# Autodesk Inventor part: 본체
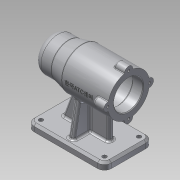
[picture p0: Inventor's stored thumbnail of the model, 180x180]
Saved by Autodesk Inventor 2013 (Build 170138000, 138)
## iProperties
Created: 2019-07
Part Number: 본체
Material: 알루미늄 6061
Document SubType Name: Modeling
Designer: Administrator
Density: 2.71 g/cm^3
Mass: 646.774 g
Surface Area: 654.083 cm^2
Volume: 238.662 cm^3
Author: Administrator
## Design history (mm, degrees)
sketch "스케치1"
  geometry: L1 (-56, 0)-(56, 0); L2 (56, 0)-(56, 21); L3 (56, 30)-(-11, 30); L4 (-11, 30)-(-31, 25); L5 (-31, 25)-(-56, 25); L6 (-56, 25)-(-56, 0); L7 (56, 21)-(41, 21); L8 (41, 21)-(41, 24); L9 (41, 24)-(-13, 24); L10 (-13, 24)-(-13, 21); L11 (-13, 21)-(-25, 21); L12 (-25, 21)-(-25, 17.5); L13 (-25, 17.5)-(-43, 17.5); L14 (-43, 17.5)-(-43, 16); L15 (-43, 16)-(-47, 16); L16 (-47, 16)-(-47, 10.5); L17 (-47, 10.5)-(-50, 10.5); L18 (-50, 10.5)-(-50, 0); L19 (56, 21)-(56, 30); 2 further points
  constraints: 38 end point, 9 horizontal, 9 vertical, 2 midpoint, 1 coincident, 1 point on line
  dimensions: "d0" = 112 distance of L1.start L1.end; "d2" = 60 diameter of L3 L1; "d3" = 50 diameter of L5 L1; "d4" = 25 distance from line of L4.end L6; "d5" = 45 distance from line of L3.end L6; "d6" = 42 diameter of L7 L1; "d7" = 48 diameter of L9 L1; "d8" = 42 diameter of L11 L1; "d9" = 35 diameter of L13 L1; "d11" = 32 diameter of L15 L1; "d12" = 21 diameter of L17 L1; "d13" = 3 distance between parallel lines of L16 L18; "d14" = 15 distance between parallel lines of L2 L8; "d15" = 54 distance between parallel lines of L8 L10; "d16" = 12 distance between parallel lines of L12 L10; "d17" = 4 distance between parallel lines of L14 L16; "d18" = 18 distance between parallel lines of L12 L14
revolve "회전1" sketch "스케치1" stored, may be unused: angle "d19" = 90 deg
sketch "스케치2"
  geometry: C1 r 21 at (0, 0) reference; C2 r 6 at (0, 30)
  constraints: 1 centre point, 1 vertical alignment
  dimensions: "d20" = 30 distance of C1.centre C2.centre; "d21" = 12 diameter of C2
extrude "돌출1" join sketch "스케치2" distance "d22" = 16; taper "d23" = 0 deg
hole "구멍1" diameter "d26" = 3.242; stored, may be unused: countersink angle "d30" = 90 deg, drill point angle "d32" = 118 deg; dims "d24" = 10, "d25" = 10, "d27" = 8, "d28" = 4, "d29" = 2, "d31" = 11
fillet "모깎기1" dims "d33" = 3
fillet "모깎기2" dims "d34" = 1
node "작업 평면1"
sketch "스케치3"
  geometry: L1 (56, 35)-(-56, 35); L2 (-56, 35)-(-56, -35); L3 (-56, -35)-(56, -35); L4 (56, -35)-(56, 35); L5 (56, 35)-(-56, -35); L6 (-56, 35)-(56, -35); 1 further point
  constraints: 12 end point, 2 midpoint, 2 parallel, 1 horizontal, 1 perpendicular
  dimensions: "d39" = 112 distance of L2.end L3.end; "d41" = 70 distance of L1.end L2.end
extrude "돌출2" join sketch "스케치3" distance "d42" = 10; taper "d43" = 0 deg
fillet "모깎기3" dims "d44" = 10
sketch "스케치4"
  geometry: A1 r 10 centre (-46, 25) between (-46, 35) and (-56, 25) reference; A2 r 10 centre (-46, -25) between (-56, -25) and (-46, -35) reference; A3 r 10 centre (46, -25) between (46, -35) and (56, -25) reference; A4 r 10 centre (46, 25) between (56, 25) and (46, 35) reference; 5 further points
  constraints: 4 coincident
hole "구멍2" sketch "스케치4" at (-46, 25), (-46, -25), (46, -25), (46, 25) diameter "d45" = 6; stored, may be unused: countersink angle "d49" = 90 deg, drill point angle "d51" = 118 deg; dims "d46" = 8, "d47" = 4, "d48" = 2, "d50" = 11
sketch "스케치5"
  geometry: L1 (-56, 25)-(-56, -25) reference; L2 (56, -25)-(56, 25) reference; L3 (-36, 4)-(31, 4); L4 (31, 4)-(31, -4); L5 (31, -4)-(-36, -4); L6 (-36, -4)-(-36, 4); 2 further points
  constraints: 8 end point, 2 parallel, 1 horizontal, 1 horizontal alignment, 1 midpoint, 1 perpendicular
  dimensions: "d52" = 25 distance between parallel lines of L2 L4; "d53" = 20 distance between parallel lines of L1 L6; "d54" = 8 distance between parallel lines of L5 L3
extrude "돌출3" join sketch "스케치5" stored distance "d55" = 10; taper "d56" = 0 deg
feature "면 기울기1" dims angle "d57" = 20 deg
chamfer "모따기1" distance "d58" = 3; stored, may be unused: second distance "d59" = 2, angle "d60" = 45 deg
sketch "스케치6"
  geometry: L1 (-80, 35)-(-73, 35) reference; L2 (-70, 32)-(-70, 25) reference; L3 (-70, 25)-(-70, -25) reference; L4 (-70, 28)-(-52.307, 24.88); 1 further point
  constraints: 2 end point, 1 point on line
  dimensions: "d61" = 7 distance from line of L4.start L1; "d62" = 100 deg angle of L2 L4
feature "리브1" sketch "스케치6" dims "d63" = 1, "d64" = 8, "d65" = 0, "d66" = 0, "d67" = 1, "d68" = 1
node "작업 평면2"
sketch "스케치7"
  geometry: L1 (33.5, 36)-(33.5, 30.171) reference; 2 further points
  constraints: 1 horizontal alignment, 1 other
  dimensions: "d69" = 42 distance from line of L1 point (-8.5, 0)
feature "엠보싱1" sketch "스케치7" dims "d70" = 0.5, "d71" = 0
fillet "모깎기4" dims "d72" = 0.3
fillet "모깎기5" dims "d73" = 3
chamfer "모따기2" distance "d74" = 1; stored, may be unused: second distance "d75" = 2, angle "d76" = 45 deg
fillet "모깎기6" dims "d77" = 10
fillet "모깎기7" dims "d78" = 3
fillet "모깎기8" dims "d79" = 3
fillet "모깎기9" dims "d80" = 3
node "솔리드1"
pattern_circular "원형 패턴1" dims "d36" = 360 deg
mirror "대칭1"
